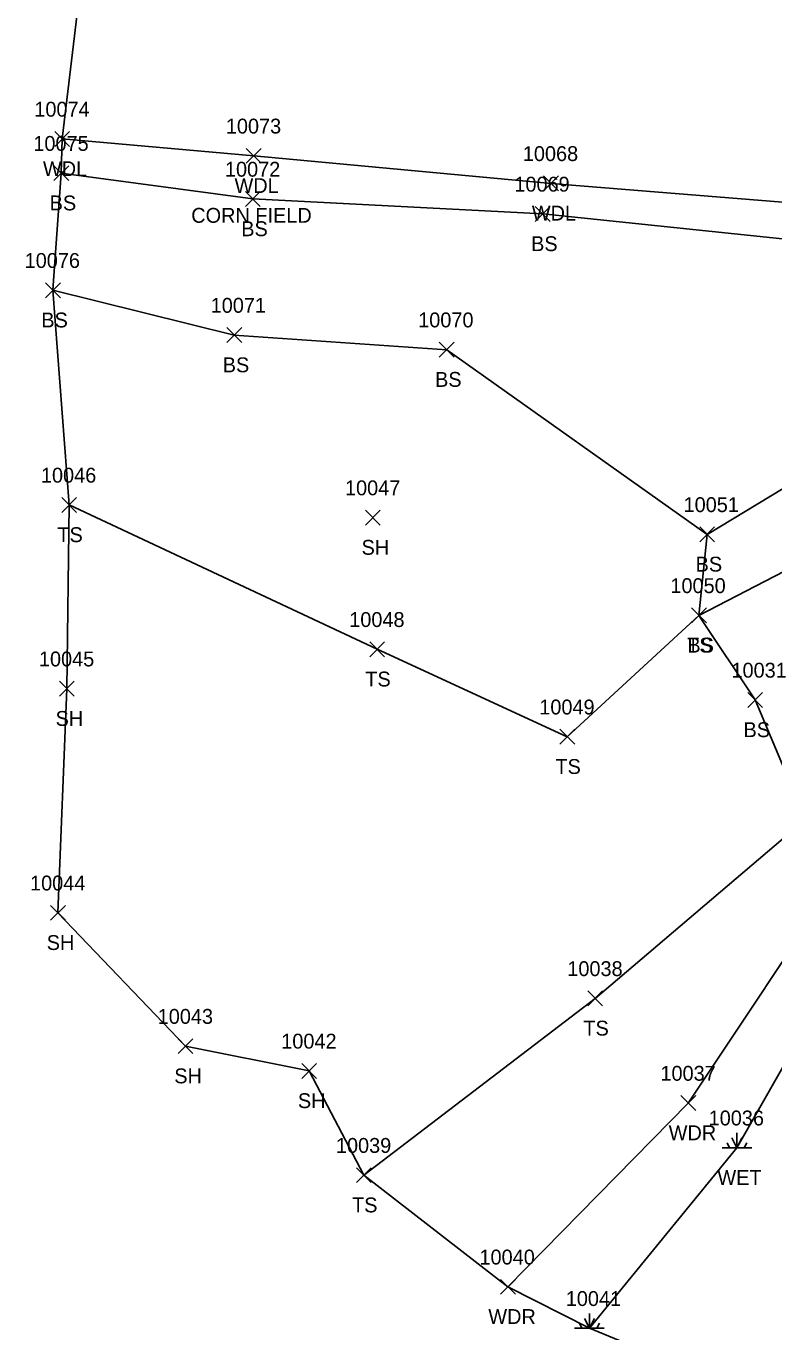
# Model space of a CAD drawing. Extents: x 1482574 to 1485769, y 580696 to 595649.
# Drawn here: x 1484913.3 to 1485013.9, y 580799.4 to 580974.9 of the extents above; entities that cross this region are included whole.
import ezdxf

# ---------------------------------------------------------------- set-up
doc = ezdxf.new("R2010")
doc.units = 0
for name, color, linetype in [('L_A', 7, 'Continuous'), ('L_C', 7, 'Continuous'), ('L_I', 7, 'Continuous'), ('L_TIC', 7, 'Continuous'), ('LAWA', 7, 'Continuous'), ('LELB', 7, 'Continuous'), ('LSOGP', 7, 'Continuous'), ('LWET', 7, 'Continuous')]:
    doc.layers.add(name, color=color, linetype=linetype)

msp = doc.modelspace()

# ---------------------------------------------------------------- linework, layer by layer
at = {"layer": 'L_TIC'}
for points in [[(1484917.18, 580958.77), (1484919.18, 580960.77)], [(1484919.18, 580958.77), (1484917.18, 580960.77)], [(1484942.93, 580956.5), (1484944.93, 580958.5)], [(1484944.93, 580956.5), (1484942.93, 580958.5)], [(1484917.05, 580954.17), (1484919.05, 580956.17)], [(1484919.05, 580954.17), (1484917.05, 580956.17)], [(1484982.9, 580952.8), (1484984.9, 580954.8)], [(1484984.9, 580952.8), (1484982.9, 580954.8)], [(1484942.81, 580950.7), (1484944.81, 580952.7)], [(1484944.81, 580950.7), (1484942.81, 580952.7)], [(1484981.78, 580948.69), (1484983.78, 580950.69)], [(1484983.78, 580948.69), (1484981.78, 580950.69)], [(1484915.93, 580938.43), (1484917.93, 580940.43)], [(1484917.93, 580938.43), (1484915.93, 580940.43)], [(1484940.32, 580932.4), (1484942.32, 580934.4)], [(1484942.32, 580932.4), (1484940.32, 580934.4)], [(1484968.87, 580930.44), (1484970.87, 580932.44)], [(1484970.87, 580930.44), (1484968.87, 580932.44)], [(1484918.12, 580909.56), (1484920.12, 580911.56)], [(1484920.12, 580909.56), (1484918.12, 580911.56)], [(1484958.95, 580907.86), (1484960.95, 580909.86)], [(1484960.95, 580907.86), (1484958.95, 580909.86)], [(1485003.9, 580905.6), (1485005.9, 580907.6)], [(1485005.9, 580905.6), (1485003.9, 580907.6)], [(1485003.9, 580905.6), (1485005.9, 580907.6)], [(1485005.9, 580905.6), (1485003.9, 580907.6)], [(1485002.79, 580894.71), (1485004.79, 580896.71)], [(1485004.79, 580894.71), (1485002.79, 580896.71)], [(1485002.79, 580894.71), (1485004.79, 580896.71)], [(1485004.79, 580894.71), (1485002.79, 580896.71)], [(1484959.52, 580890.15), (1484961.52, 580892.15)], [(1484961.52, 580890.15), (1484959.52, 580892.15)], [(1484917.8, 580884.85), (1484919.8, 580886.85)], [(1484919.8, 580884.85), (1484917.8, 580886.85)], [(1485010.34, 580883.34), (1485012.34, 580885.34)], [(1485012.34, 580883.34), (1485010.34, 580885.34)], [(1484985.08, 580878.39), (1484987.08, 580880.39)], [(1484987.08, 580878.39), (1484985.08, 580880.39)], [(1484916.61, 580854.72), (1484918.61, 580856.72)], [(1484918.61, 580854.72), (1484916.61, 580856.72)], [(1484988.84, 580843.21), (1484990.84, 580845.21)], [(1484990.84, 580843.21), (1484988.84, 580845.21)], [(1484933.76, 580836.79), (1484935.76, 580838.79)], [(1484935.76, 580836.79), (1484933.76, 580838.79)], [(1484950.38, 580833.46), (1484952.38, 580835.46)], [(1484952.38, 580833.46), (1484950.38, 580835.46)], [(1485001.36, 580829.14), (1485003.36, 580831.14)], [(1485003.36, 580829.14), (1485001.36, 580831.14)], [(1484957.74, 580819.44), (1484959.74, 580821.44)], [(1484959.74, 580819.44), (1484957.74, 580821.44)], [(1484977.11, 580804.43), (1484979.11, 580806.43)], [(1484979.11, 580804.43), (1484977.11, 580806.43)]]:
    msp.add_lwpolyline(points, dxfattribs=at)
at = {"layer": 'LAWA'}
for points in [[(1485040.69, 580872.82), (1485034.72, 580889.44), (1485047.48, 580909.95), (1485053.06, 580939.09), (1485031.71, 580949.93), (1484983.9, 580953.8), (1484943.93, 580957.5), (1484918.18, 580959.77)], [(1485040.69, 580872.82), (1485023.17, 580861.4), (1485002.36, 580830.14), (1484978.11, 580805.43)]]:
    msp.add_lwpolyline(points, dxfattribs=at)
at = {"layer": 'LELB'}
for points in [[(1485018.13, 580868.27), (1485011.34, 580884.34), (1485003.79, 580895.71), (1485004.9, 580906.6), (1485025.54, 580919.11), (1485053.06, 580939.09), (1485031.33, 580944.62), (1484982.78, 580949.69), (1484943.81, 580951.7), (1484918.05, 580955.17)], [(1485004.9, 580906.6), (1484969.87, 580931.44), (1484941.32, 580933.4), (1484916.93, 580939.43)], [(1484919.12, 580910.56), (1484960.52, 580891.15), (1484986.08, 580879.39), (1485003.79, 580895.71), (1485026.72, 580907.58), (1485047.48, 580909.95), (1485087.41, 580935.49)], [(1485034.72, 580889.44), (1485018.13, 580868.27), (1484989.84, 580844.21), (1484958.74, 580820.44)]]:
    msp.add_lwpolyline(points, dxfattribs=at)
at = {"layer": 'LSOGP'}
msp.add_lwpolyline([(1485033.74, 580781.41), (1484989.06, 580799.85), (1484978.11, 580805.43), (1484958.74, 580820.44), (1484951.38, 580834.46), (1484934.76, 580837.79), (1484917.61, 580855.72), (1484918.8, 580885.85), (1484919.12, 580910.56), (1484916.93, 580939.43), (1484918.05, 580955.17), (1484918.18, 580959.77), (1484922.23, 580993.54)], dxfattribs=at)
at = {"layer": 'LWET'}
for p, q in [((1485008.89, 580824.13), (1485008.89, 580826.13)), ((1485007.89, 580824.13), (1485007.56, 580824.8)), ((1485008.89, 580824.13), (1485008.22, 580825.47)), ((1485008.89, 580824.13), (1485009.56, 580825.47)), ((1485009.89, 580824.13), (1485010.22, 580824.8)), ((1485010.89, 580824.13), (1485006.89, 580824.13)), ((1484989.06, 580799.85), (1484989.06, 580801.85)), ((1484991.06, 580799.85), (1484987.06, 580799.85)), ((1484988.06, 580799.85), (1484987.73, 580800.52)), ((1484989.06, 580799.85), (1484988.4, 580801.18)), ((1484989.06, 580799.85), (1484989.73, 580801.18)), ((1484990.06, 580799.85), (1484990.4, 580800.52))]:
    msp.add_line(p, q, dxfattribs=at)
msp.add_lwpolyline([(1485033.74, 580781.41), (1485044.09, 580799.5), (1485049.07, 580817.91), (1485054.22, 580839.73), (1485053.83, 580844.64), (1485050.32, 580856.37), (1485045.55, 580871.32), (1485026.88, 580855.73), (1485008.89, 580824.13), (1484989.06, 580799.85)], dxfattribs=at)

# ---------------------------------------------------------------- texts
at = {"layer": 'L_A'}
for s, p in [('WDL', (1484915.59, 580954.77)), ('WDL', (1484941.35, 580952.5)), ('BS', (1484916.49, 580950.17)), ('WDL', (1484981.32, 580948.8)), ('BS', (1484942.25, 580946.7)), ('BS', (1484981.22, 580944.69)), ('BS', (1484915.37, 580934.43)), ('BS', (1484939.76, 580928.4)), ('BS', (1484968.31, 580926.44)), ('TS', (1484917.53, 580905.56)), ('SH', (1484958.43, 580903.86)), ('BS', (1485003.34, 580901.6)), ('BS', (1485003.34, 580901.6)), ('TS', (1485002.2, 580890.71)), ('BS', (1485002.23, 580890.71)), ('TS', (1484958.93, 580886.15)), ('SH', (1484917.29, 580880.85)), ('BS', (1485009.78, 580879.34)), ('TS', (1484984.49, 580874.39)), ('SH', (1484916.1, 580850.72)), ('TS', (1484988.25, 580839.21)), ('SH', (1484933.25, 580832.79)), ('SH', (1484949.87, 580829.46)), ('WDR', (1484999.72, 580825.14)), ('WET', (1485006.27, 580819.13)), ('TS', (1484957.15, 580815.44)), ('WDR', (1484975.47, 580800.43))]:
    msp.add_text(s, height=2, dxfattribs=at).set_placement(p)
at = {"layer": 'L_C'}
msp.add_text('CORN FIELD', height=2, dxfattribs=at).set_placement((1484935.53, 580948.5))
at = {"layer": 'L_I'}
for s, p in [('10074', (1484914.43, 580962.77)), ('10073', (1484940.18, 580960.5)), ('10075', (1484914.3, 580958.17)), ('10068', (1484980.11, 580956.8)), ('10072', (1484940.06, 580954.7)), ('10069', (1484978.97, 580952.69)), ('10076', (1484913.13, 580942.43)), ('10071', (1484938.14, 580936.4)), ('10070', (1484966.04, 580934.44)), ('10046', (1484915.32, 580913.56)), ('10047', (1484956.2, 580911.86)), ('10051', (1485001.72, 580909.6)), ('10051', (1485001.72, 580909.6)), ('10050', (1484999.95, 580898.71)), ('10050', (1484999.95, 580898.71)), ('10048', (1484956.77, 580894.15)), ('10045', (1484915.05, 580888.85)), ('10031', (1485008.16, 580887.34)), ('10049', (1484982.32, 580882.39)), ('10044', (1484913.86, 580858.72)), ('10038', (1484986.09, 580847.21)), ('10043', (1484931.02, 580840.79)), ('10042', (1484947.63, 580837.46)), ('10037', (1484998.61, 580833.14)), ('10036', (1485005.09, 580827.13)), ('10039', (1484954.98, 580823.44)), ('10040', (1484974.28, 580808.43)), ('10041', (1484985.88, 580802.85))]:
    msp.add_text(s, height=2, dxfattribs=at).set_placement(p)

doc.saveas('drawing.dxf')
